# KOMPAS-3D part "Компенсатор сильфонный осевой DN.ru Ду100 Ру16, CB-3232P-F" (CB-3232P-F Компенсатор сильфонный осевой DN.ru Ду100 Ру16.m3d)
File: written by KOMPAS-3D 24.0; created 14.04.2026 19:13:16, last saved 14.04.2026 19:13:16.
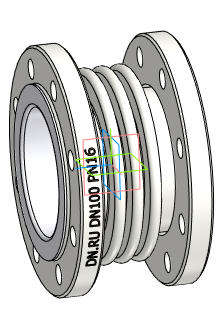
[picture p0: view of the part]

Document properties: Автор: DN.RU; Полное имя файла: D:\PROJECT CAD\DN.RU\..199(ACTUALE). CB-3232P-F Компенсатор сильфонный осевой DN.ru\Исходники\DN100\CB-3232P-F Компенсатор сильфонный осевой DN.ru Ду100 Ру16.m3d

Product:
- Body: Твердое тело1  | qty 1
    Масса: 11.179222
- Part/product: Компенсатор сильфонный осевой DN.ru Ду100 Ру16  | designation CB-3232P-F
    Масса: 9
    Раздел спецификации: Прочие изделия
    Комментарий: D140-02141
    Примечание: D140-02141
    additional columns: Типовые

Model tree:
1. Твердое тело1  (labels: Твердое тело1)

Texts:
  CB-3232P-F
